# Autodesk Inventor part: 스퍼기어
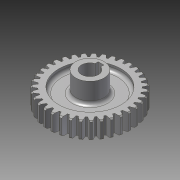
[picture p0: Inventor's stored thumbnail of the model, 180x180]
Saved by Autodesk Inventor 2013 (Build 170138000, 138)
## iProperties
Created: 2013-08
Part Number: 스퍼기어
Material: 강
Document SubType Name: Modeling
Designer: 한국산업디자인학원
Categories: <?xml version="1.0" encoding="UTF-16"?> <MemberInstance><Categories><FamilyTemplate><FamilyTemplateParameter ValueType="xs:double" Id="1" ObjectReferenceKey="da
Density: 1 g/cm^3
CustomPartVersion: 1
Author: 한국산업디자인학원
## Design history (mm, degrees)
sketch "Sketch1"
  geometry: C1 r 37 at (0, 0)
  constraints: 1 centre point
  dimensions: "d0" = 74 diameter of C1 (= da_da)
extrude "Extrusion1" new body sketch "Sketch1" distance "d1" = 15 (= da_b); taper "d2" = 0 deg
chamfer "모따기1" distance "d49" = 1; stored, may be unused: second distance "d50" = 2, angle "d51" = 45 deg
workplane "Work Plane2"
feature "피치 지름" dims "d4" = 10, "d5" = 0
workplane "Work Plane8"
workplane "Work Plane9"
feature "스퍼 기어" dims "da_b" = 15, "da_d" = 70, "da_aw" = 70, "da_da" = 74, "da_df" = 65, "da_dw" = 70, angle "da_beta" = 0 deg, "da_lefttooth" = 0, "da_righttooth" = 0
sketch "스케치3"
  geometry: C1 r 27.5 at (0, 0); A1 r 32.5 centre (0, 0) between (9.347, 31.127) and (7.941, 31.515) reference
  constraints: 1 centre point, 1 coincident
  dimensions: "d52" = 55 diameter of C1
extrude "돌출2" cut sketch "스케치3" distance "d54" = 5; taper "d55" = 0 deg
sketch "스케치4"
  geometry: C1 r 27.5 at (0, 0); A1 r 36 centre (0, 0) between (-5.215, 35.62) and (-7.633, 35.181) reference
  constraints: 1 centre point, 1 coincident
  dimensions: "d56" = 55 diameter of C1
extrude "돌출3" cut sketch "스케치4" distance "d58" = 5; taper "d59" = 0 deg
node "작업 평면11"
sketch "스케치5"
  geometry: C1 r 12.5 at (0, 0); 1 further point
  constraints: 1 centre point, 1 coincident
  dimensions: "d61" = 25 diameter of C1
extrude "돌출4" join sketch "스케치5" distance "d63" = 31; taper "d64" = 0 deg
sketch "스케치6"
  geometry: L1 (-2.5, 7.071)-(-2.5, 9.8); L2 (-2.5, 9.8)-(2.5, 9.8); L3 (2.5, 9.8)-(2.5, 7.071); C1 r 12.5 at (0, 0) reference; A1 r 7.5 centre (0, 0) between (-2.5, 7.071) and (2.5, 7.071); 1 further point
  constraints: 6 end point, 2 point on circle, 1 centre point, 1 coincident, 1 midpoint, 1 parallel, 1 perpendicular, 1 vertical, 1 vertical alignment
  dimensions: "d65" = 15 diameter of A1; "d67" = 5 distance between parallel lines of L1 L3; "d68" = 17.3 dimension on A1 L2
extrude "돌출5" cut sketch "스케치6" stored distance "d69" = 31; taper "d70" = 0 deg
fillet "모깎기1" dims "d71" = 3
body "Solid1"
sketch "Sketch2"
  geometry: C1 r 37 at (0, 0) reference; C2 r 35 at (0, 0)
  constraints: 1 centre point, 1 coincident
  dimensions: "d3" = 70 diameter of C2 (= da_dw)
body "Srf1"
other parameters: "d17" = 0, "d34" = 0.8976 (computed from da_z), "d39" = 0, "d41" = 0, "d47" = 0, "d48" = 0, "d60" = 3
